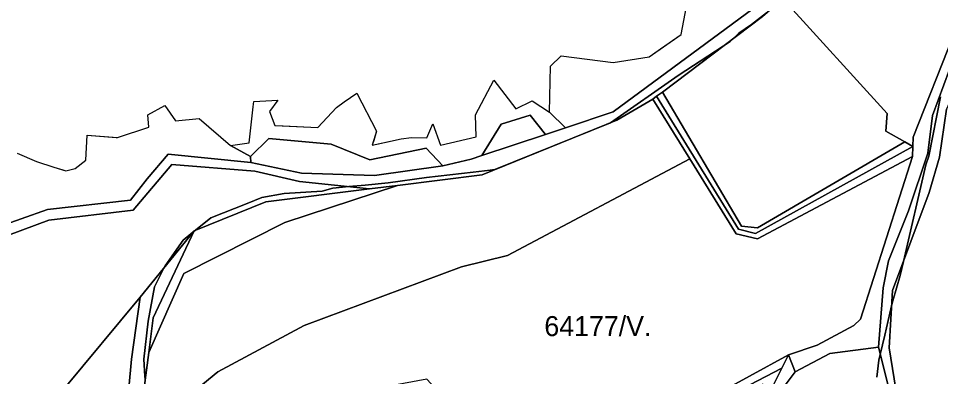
# Model space of a CAD drawing. Extents: x -502026 to -497664, y -1143484 to -1138019.
# Drawn here: x -499892.7 to -499523.9, y -1138710.6 to -1138567.4 of the extents above; entities that cross this region are included whole.
import ezdxf

# ---------------------------------------------------------------- set-up
doc = ezdxf.new("R2010")
doc.units = 0
for name, color, linetype in [('31', 7, 'Continuous'), ('37', 7, 'Continuous'), ('43', 7, 'Continuous'), ('55', 7, 'Continuous'), ('62', 7, 'Continuous')]:
    doc.layers.add(name, color=color, linetype=linetype)

msp = doc.modelspace()

# ---------------------------------------------------------------- linework, layer by layer
at = {"layer": '31'}
msp.add_lwpolyline([(-499537.01, -1138745.37), (-499557.37, -1138744.4), (-499552.1, -1138790.55), (-499558.38, -1138790.37), (-499566.24, -1138743.1), (-499580.14, -1138748.95), (-499588.16, -1138761.99), (-499591.11, -1138774.54), (-499594.7, -1138775.32), (-499599.24, -1138776.76), (-499605.61, -1138760.41), (-499600.27, -1138741.69), (-499589.7, -1138718.79), (-499582.04, -1138708.7), (-499568.17, -1138701.36), (-499548.75, -1138698.77)], close=True, dxfattribs=at)
at = {"layer": '37'}
for points in [[(-499624.19, -1138623.47), (-499697.07, -1138662.14), (-499715.47, -1138666.65), (-499778.38, -1138690.2), (-499812.98, -1138708.74), (-499828.03, -1138721.09), (-499841.22, -1138736.39), (-499842.46, -1138715.08), (-499840.59, -1138700.98), (-499826.55, -1138669.42), (-499786.16, -1138649.02), (-499741.11, -1138634.19), (-499707.24, -1138629.85), (-499653.4, -1138608.06), (-499638.95, -1138599.65)], [(-499584.72, -1138701.93), (-499647.14, -1138735.95), (-499688.61, -1138754.3), (-499700.38, -1138742.85), (-499700.56, -1138742.65), (-499729.36, -1138711.56), (-499750.17, -1138715.52), (-499792.14, -1138739.41), (-499812.14, -1138754.89), (-499835.52, -1138777.51), (-499839.65, -1138763.23), (-499841.22, -1138736.39), (-499828.03, -1138721.09), (-499812.98, -1138708.74), (-499778.38, -1138690.2), (-499715.47, -1138666.65), (-499697.07, -1138662.14), (-499624.19, -1138623.47), (-499605.59, -1138653.48), (-499597.17, -1138655.53), (-499535.12, -1138622.58), (-499555.94, -1138687.68), (-499558.61, -1138690.15), (-499573.23, -1138697.97)], [(-499587.35, -1138707.16), (-499644.97, -1138737.18), (-499686.59, -1138756.26), (-499688.61, -1138754.3), (-499647.14, -1138735.95), (-499584.72, -1138701.93)], [(-499592.6, -1138717.6), (-499594.93, -1138713.6), (-499648.25, -1138741.88), (-499686.17, -1138759.35), (-499686.59, -1138756.26), (-499644.97, -1138737.18), (-499587.35, -1138707.16)]]:
    msp.add_lwpolyline(points, close=True, dxfattribs=at)
msp.add_lwpolyline([(-499513.48, -1138746.91), (-499530.87, -1138745.67), (-499537.01, -1138745.37), (-499544.51, -1138699.06), (-499543.1, -1138676.2), (-499528.49, -1138637.04), (-499524.27, -1138622.83), (-499521.46, -1138603.68)], dxfattribs=at)
at = {"layer": '43'}
for points in [[(-499537.01, -1138745.37), (-499548.75, -1138698.77), (-499546.8, -1138675.05), (-499544.76, -1138664.32), (-499536.74, -1138644.34), (-499529, -1138621.3), (-499527.08, -1138606.23), (-499515.85, -1138575.58), (-499509.34, -1138543.14), (-499505.39, -1138478.58), (-499500.91, -1138476.52), (-499503.34, -1138544.42), (-499509.59, -1138576.6), (-499521.46, -1138603.68), (-499524.27, -1138622.83), (-499528.49, -1138637.04), (-499543.1, -1138676.2), (-499544.51, -1138699.06)], [(-499593.97, -1138559.74), (-499654.8, -1138604.74), (-499673.9, -1138611.09), (-499680.28, -1138604.82), (-499679.86, -1138586.43), (-499675.7, -1138582.4), (-499654.86, -1138585.01), (-499640.42, -1138582.71), (-499627.69, -1138573.83), (-499625.48, -1138562.56), (-499613.17, -1138563.39), (-499607.33, -1138545.31)], [(-499680.28, -1138604.82), (-499673.9, -1138611.09), (-499681.92, -1138613.76), (-499688.06, -1138606.1), (-499699.68, -1138609.68), (-499707.38, -1138622.23), (-499711.61, -1138623.64), (-499722.97, -1138626.32), (-499729.68, -1138619.26), (-499752.14, -1138623.98), (-499767.65, -1138617.67), (-499792.55, -1138615.37), (-499799.95, -1138622.52), (-499807.93, -1138618.15), (-499800.4, -1138617.07), (-499798.76, -1138602.68), (-499798.52, -1138600.54), (-499788.96, -1138600), (-499792.34, -1138604.55), (-499790.13, -1138610.19), (-499772.9, -1138610.93), (-499765.45, -1138602.95), (-499762.36, -1138600.68), (-499757.4, -1138597.3), (-499749.54, -1138612.41), (-499751.18, -1138618.11), (-499739.68, -1138615.48), (-499735.53, -1138614.94), (-499729.33, -1138615.11), (-499726.94, -1138609.57), (-499723.96, -1138618.06), (-499709.62, -1138614.77), (-499709.94, -1138605.87), (-499702.52, -1138592.02), (-499693.79, -1138603.47), (-499687.17, -1138600.38)], [(-499840.59, -1138700.98), (-499838.76, -1138687.12), (-499822.42, -1138652.25), (-499793.82, -1138640.76), (-499752.34, -1138635.48), (-499741.11, -1138634.19), (-499786.16, -1138649.02), (-499826.55, -1138669.42)], [(-499840.59, -1138700.98), (-499842.46, -1138715.08), (-499841.22, -1138736.39), (-499850.82, -1138739.83), (-499847.44, -1138703.59), (-499843.96, -1138678.89), (-499822.42, -1138652.25), (-499838.76, -1138687.12)], [(-499850.82, -1138739.83), (-499854.46, -1138753.4), (-499851.53, -1138767.96), (-499852.16, -1138786.6), (-499846.16, -1138840.24), (-499836.59, -1138882.65), (-499833.88, -1138891.94), (-499851.98, -1138903.25), (-499853.25, -1138901.83), (-499850.82, -1138889.32), (-499863.78, -1138868.14), (-499864.68, -1138855.11), (-499886.12, -1138799.3), (-499868.63, -1138776.44), (-499869.78, -1138751.79), (-499874.85, -1138715.81), (-499843.96, -1138678.89), (-499847.44, -1138703.59)]]:
    msp.add_lwpolyline(points, close=True, dxfattribs=at)
for points in [[(-499893.2, -1138621.3), (-499885.45, -1138624.59), (-499878.49, -1138626.81), (-499873.75, -1138628.32), (-499870, -1138627.32), (-499865.68, -1138624.01), (-499865.19, -1138614.05), (-499853.1, -1138614.98), (-499840.5, -1138610.84), (-499840.96, -1138605.91), (-499834.12, -1138602.25), (-499829.88, -1138608.36), (-499820.41, -1138607.36), (-499807.93, -1138618.15), (-499799.95, -1138622.52), (-499799.7, -1138624.94), (-499832.76, -1138621.63), (-499841.19, -1138631.46), (-499847.82, -1138640.02), (-499881.09, -1138643.72), (-499902.28, -1138651.26)], [(-499902.54, -1138656.11), (-499880.58, -1138648.07), (-499846.81, -1138644), (-499831.31, -1138625.84), (-499798.18, -1138628.43), (-499780.24, -1138632.61), (-499752.34, -1138635.48), (-499793.82, -1138640.76), (-499822.42, -1138652.25), (-499843.96, -1138678.89), (-499874.85, -1138715.81), (-499893.13, -1138737.65)]]:
    msp.add_lwpolyline(points, dxfattribs=at)
at = {"layer": '55'}
for points in [[(-499516.1, -1138443.28), (-499531.49, -1138469.59), (-499539.85, -1138477.89), (-499556.38, -1138512.27), (-499565.83, -1138540.79), (-499586.97, -1138559.44), (-499595.12, -1138566.64), (-499635.16, -1138596.8), (-499637.44, -1138598.51), (-499638.95, -1138599.65), (-499653.4, -1138608.06), (-499707.24, -1138629.85), (-499741.11, -1138634.19), (-499752.34, -1138635.48), (-499780.24, -1138632.61), (-499798.18, -1138628.43), (-499831.31, -1138625.84), (-499846.81, -1138644), (-499880.58, -1138648.07), (-499902.54, -1138656.11)], [(-499902.28, -1138651.26), (-499881.09, -1138643.72), (-499847.82, -1138640.02), (-499841.19, -1138631.46), (-499832.76, -1138621.63), (-499799.7, -1138624.94), (-499779.53, -1138629.26), (-499750.29, -1138630.15), (-499722.97, -1138626.32), (-499711.61, -1138623.64), (-499707.38, -1138622.23), (-499681.92, -1138613.76), (-499673.9, -1138611.09), (-499654.8, -1138604.74), (-499593.97, -1138559.74), (-499570.42, -1138540.15), (-499561.49, -1138514.45), (-499549.8, -1138488.49), (-499542.59, -1138476.1), (-499532.51, -1138465.69), (-499525.63, -1138450.02), (-499520.54, -1138441.91)], [(-499515.85, -1138575.58), (-499527.08, -1138606.23), (-499529, -1138621.3), (-499536.74, -1138644.34), (-499544.76, -1138664.32), (-499546.8, -1138675.05), (-499548.75, -1138698.77), (-499568.17, -1138701.36), (-499582.04, -1138708.7), (-499584.72, -1138701.93), (-499573.23, -1138697.97), (-499558.61, -1138690.15), (-499555.94, -1138687.68), (-499535.12, -1138622.58), (-499534.99, -1138618.61), (-499534.87, -1138614.79), (-499518.66, -1138574.05)], [(-499592.6, -1138717.6), (-499587.35, -1138707.16), (-499584.72, -1138701.93), (-499582.04, -1138708.7), (-499589.7, -1138718.79)]]:
    msp.add_lwpolyline(points, dxfattribs=at)
for points in [[(-499502.32, -1138462.17), (-499511.25, -1138477.75), (-499514.06, -1138542.37), (-499518.66, -1138574.05), (-499534.87, -1138614.79), (-499534.99, -1138618.61), (-499538.24, -1138616.75), (-499545.72, -1138612.49), (-499545.21, -1138605.34), (-499586.97, -1138559.44), (-499565.83, -1138540.79), (-499556.38, -1138512.27), (-499539.85, -1138477.89), (-499531.49, -1138469.59), (-499516.1, -1138443.28)], [(-499538.24, -1138616.75), (-499597.17, -1138651.06), (-499603.49, -1138650.39), (-499635.16, -1138596.8), (-499595.12, -1138566.64), (-499586.97, -1138559.44), (-499545.21, -1138605.34), (-499545.72, -1138612.49)], [(-499534.99, -1138618.61), (-499535.12, -1138622.58), (-499597.17, -1138655.53), (-499605.59, -1138653.48), (-499624.19, -1138623.47), (-499638.95, -1138599.65), (-499637.44, -1138598.51), (-499604.7, -1138651.7), (-499597.93, -1138653.36)], [(-499538.24, -1138616.75), (-499534.99, -1138618.61), (-499597.93, -1138653.36), (-499604.7, -1138651.7), (-499637.44, -1138598.51), (-499635.16, -1138596.8), (-499603.49, -1138650.39), (-499597.17, -1138651.06)], [(-499681.92, -1138613.76), (-499707.38, -1138622.23), (-499699.68, -1138609.68), (-499688.06, -1138606.1)], [(-499722.97, -1138626.32), (-499750.29, -1138630.15), (-499779.53, -1138629.26), (-499799.7, -1138624.94), (-499799.95, -1138622.52), (-499792.55, -1138615.37), (-499767.65, -1138617.67), (-499752.14, -1138623.98), (-499729.68, -1138619.26)]]:
    msp.add_lwpolyline(points, close=True, dxfattribs=at)
at = {"layer": '62'}
for points in [[(-499893.2, -1138621.3), (-499885.45, -1138624.59), (-499878.49, -1138626.81), (-499875.01, -1138627.92), (-499873.75, -1138628.32), (-499870, -1138627.32), (-499867, -1138625.02), (-499865.68, -1138624.01), (-499865.19, -1138614.05), (-499853.67, -1138614.94), (-499853.1, -1138614.98), (-499840.99, -1138611), (-499840.5, -1138610.84), (-499840.96, -1138605.91), (-499834.12, -1138602.25), (-499829.88, -1138608.36), (-499820.41, -1138607.36), (-499807.93, -1138618.15), (-499800.4, -1138617.07), (-499798.76, -1138602.68), (-499798.52, -1138600.54), (-499788.96, -1138600), (-499792.34, -1138604.55), (-499790.13, -1138610.19), (-499786.86, -1138610.33), (-499772.9, -1138610.93), (-499765.45, -1138602.95), (-499762.36, -1138600.68), (-499757.4, -1138597.3), (-499749.54, -1138612.41), (-499750.61, -1138616.13), (-499751.18, -1138618.11), (-499744.4, -1138616.56), (-499739.68, -1138615.48), (-499735.53, -1138614.94), (-499729.33, -1138615.11), (-499726.94, -1138609.57), (-499723.96, -1138618.06), (-499709.62, -1138614.77), (-499709.94, -1138605.87), (-499702.52, -1138592.02), (-499693.79, -1138603.47), (-499687.17, -1138600.38), (-499680.28, -1138604.82), (-499679.86, -1138586.43), (-499675.7, -1138582.4), (-499654.86, -1138585.01), (-499640.42, -1138582.71), (-499635.92, -1138579.57), (-499627.69, -1138573.83), (-499625.48, -1138562.56)], [(-499842, -1138711.59), (-499842.09, -1138710.37), (-499842.53, -1138703.62), (-499840.81, -1138688.37), (-499838.28, -1138674.75), (-499834.5, -1138667.19), (-499834.03, -1138666.25), (-499826.81, -1138656), (-499822.94, -1138652.89), (-499822.59, -1138652.61), (-499821.85, -1138652.02), (-499815.75, -1138647.12), (-499801.18, -1138641.31), (-499795.37, -1138639), (-499786.44, -1138637.37), (-499771.16, -1138636.5), (-499766.91, -1138635.25), (-499760.53, -1138634.64), (-499754.04, -1138634.01), (-499744.81, -1138633.12), (-499729.5, -1138631), (-499710.81, -1138628.87), (-499704.08, -1138628.03), (-499702.12, -1138627.78), (-499655.88, -1138609.06), (-499628.81, -1138590.25), (-499610.87, -1138578.5), (-499608, -1138576.62), (-499606.81, -1138575.44), (-499605.57, -1138574.22), (-499604.59, -1138573.25), (-499599.5, -1138569.75), (-499593.45, -1138565.16)], [(-499593.45, -1138565.16), (-499599.5, -1138569.75), (-499604.59, -1138573.25), (-499605.57, -1138574.22), (-499606.81, -1138575.44), (-499608, -1138576.62), (-499610.87, -1138578.5), (-499628.81, -1138590.25), (-499655.88, -1138609.06), (-499702.12, -1138627.78), (-499704.08, -1138628.03), (-499710.81, -1138628.87), (-499729.5, -1138631), (-499744.81, -1138633.12), (-499754.04, -1138634.01), (-499760.53, -1138634.64), (-499766.91, -1138635.25), (-499771.16, -1138636.5), (-499786.44, -1138637.37), (-499795.37, -1138639), (-499801.18, -1138641.31), (-499815.75, -1138647.12), (-499821.85, -1138652.02), (-499822.59, -1138652.61), (-499822.94, -1138652.89), (-499826.81, -1138656), (-499834.03, -1138666.25), (-499834.5, -1138667.19), (-499838.28, -1138674.75), (-499840.81, -1138688.37), (-499842.53, -1138703.62), (-499842.09, -1138710.37), (-499842, -1138711.59)], [(-499549.37, -1138710.87), (-499548.53, -1138704), (-499548, -1138701.73), (-499546.21, -1138694.05), (-499543.48, -1138682.29), (-499543, -1138680.25), (-499540.03, -1138670.12), (-499538.74, -1138664.51), (-499529.84, -1138625.87), (-499528.56, -1138622.5), (-499523.87, -1138598.75)], [(-499523.87, -1138598.75), (-499528.56, -1138622.5), (-499529.84, -1138625.87), (-499538.74, -1138664.51), (-499540.03, -1138670.12), (-499543, -1138680.25), (-499543.48, -1138682.29), (-499546.21, -1138694.05), (-499548, -1138701.73), (-499548.53, -1138704), (-499549.37, -1138710.87)]]:
    msp.add_lwpolyline(points, dxfattribs=at)

# ---------------------------------------------------------------- texts
msp.add_text('64177/V.', height=8, dxfattribs=at).set_placement((-499682.36, -1138694.4))

doc.saveas('drawing.dxf')
